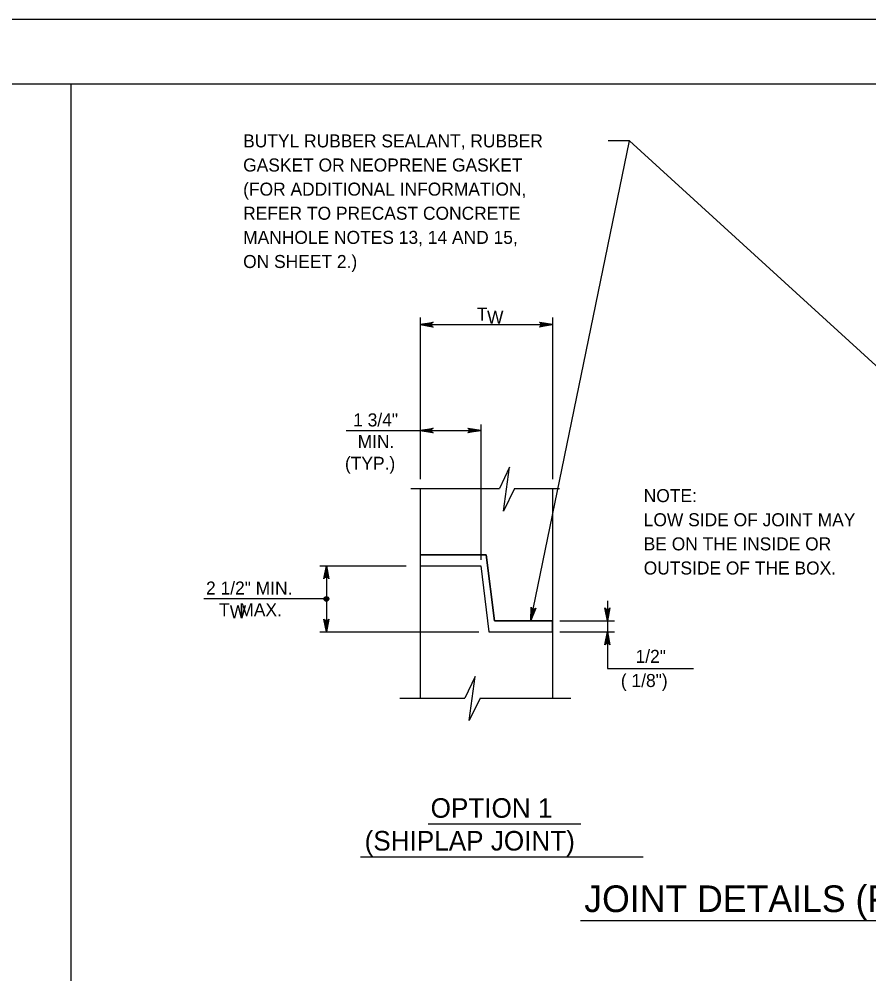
# Model space of a CAD drawing. Extents: x 2106427 to 2114911, y 988717 to 990787.
# Drawn here: x 2112951 to 2113594, y 990066 to 990787 of the extents above; entities that cross this region are included whole.
import ezdxf

# ---------------------------------------------------------------- set-up
doc = ezdxf.new("R2010")
doc.units = 0
for name, color, linetype in [('1', 7, 'Continuous'), ('3', 7, 'Continuous'), ('PLT-BNDY', 7, 'Continuous')]:
    doc.layers.add(name, color=color, linetype=linetype)

msp = doc.modelspace()

# ---------------------------------------------------------------- linework, layer by layer
at = {"layer": '1'}
for p, q in [((2112990.34, 990738.11), (2112990.34, 989231.02)), ((2113668.04, 990462.73), (2113413.04, 990695.31)), ((2113254.61, 990561.73), (2113254.61, 990439.56)), ((2113254.61, 990556.37), (2113354.61, 990556.37)), ((2113354.61, 990561.73), (2113354.61, 990439.56)), ((2113300.45, 990480.77), (2113300.45, 990378.46)), ((2113198.59, 990476.36), (2113300.45, 990476.36)), ((2113247.58, 990432.37), (2113314.54, 990432.37)), ((2113254.61, 990432.37), (2113254.61, 990274.03)), ((2113326.08, 990432.37), (2113360.05, 990432.37)), ((2113354.61, 990432.37), (2113354.61, 990274.03)), ((2113254.61, 990382.37), (2113304.61, 990382.37)), ((2113304.61, 990382.37), (2113310.85, 990332.37)), ((2113178.77, 990374.03), (2113244.11, 990374.03)), ((2113183.67, 990374.03), (2113183.67, 990324.03)), ((2113254.61, 990374.03), (2113300.45, 990374.03)), ((2113300.45, 990374.03), (2113306.69, 990324.03)), ((2113183.67, 990349.03), (2113090.84, 990349.03)), ((2113396.29, 990347.49), (2113396.29, 990296.46)), ((2113310.85, 990332.37), (2113354.61, 990332.37)), ((2113360.28, 990332.37), (2113401.55, 990332.37)), ((2113178.77, 990324.03), (2113298.92, 990324.03)), ((2113306.69, 990324.03), (2113354.61, 990324.03)), ((2113360.28, 990324.03), (2113401.55, 990324.03)), ((2113396.29, 990296.46), (2113461.34, 990296.46)), ((2113239.18, 990274.03), (2113288.53, 990274.03)), ((2113300.08, 990274.03), (2113368.48, 990274.03)), ((2113260.76, 990179.08), (2113376.11, 990179.08)), ((2113209.46, 990154), (2113423.33, 990154)), ((2113375.97, 990105.8), (2113831.83, 990105.8))]:
    msp.add_line(p, q, dxfattribs=at)
for points in [[(2114651.58, 988887.71), (2114651.58, 990738.11), (2112072.84, 990738.11), (2112072.84, 988887.71), (2114651.58, 988887.71), (2114651.58, 988974.19), (2113995.41, 988974.19), (2113995.41, 989186.39), (2114651.58, 989186.39), (2114651.58, 989281.41), (2113995.41, 989281.41), (2113995.41, 988887.71), (2114253.94, 988887.71), (2114253.94, 988974.19), (2114253.94, 988887.71), (2114506.57, 988887.71), (2114506.57, 988974.19), (2114506.57, 988933.79), (2114651.58, 988933.79)], [(2113338.41, 990332.81), (2113413.04, 990695.31), (2113396.73, 990695.31)], [(2113254.61, 990556.37), (2113264.39, 990558.2), (2113264.01, 990557.94), (2113263.64, 990557.68), (2113263.44, 990557.35), (2113263.25, 990557.02), (2113263.19, 990556.69), (2113263.14, 990556.37), (2113263.19, 990556.04), (2113263.25, 990555.71), (2113263.44, 990555.38), (2113263.64, 990555.05), (2113264.01, 990554.79), (2113264.39, 990554.53), (2113254.61, 990556.37), (2113264.01, 990554.79), (2113263.64, 990555.05), (2113254.61, 990556.37), (2113263.44, 990555.38), (2113263.25, 990555.71), (2113254.61, 990556.37), (2113263.19, 990556.04), (2113263.14, 990556.37), (2113254.61, 990556.37), (2113263.19, 990556.69), (2113263.25, 990557.02), (2113254.61, 990556.37), (2113263.44, 990557.35), (2113263.64, 990557.68), (2113254.61, 990556.37), (2113264.01, 990557.94)], [(2113354.61, 990556.37), (2113344.82, 990554.53), (2113345.2, 990554.79), (2113345.57, 990555.05), (2113345.77, 990555.38), (2113345.96, 990555.71), (2113346.02, 990556.04), (2113346.08, 990556.37), (2113346.02, 990556.69), (2113345.96, 990557.02), (2113345.77, 990557.35), (2113345.57, 990557.68), (2113345.2, 990557.94), (2113344.82, 990558.2), (2113354.61, 990556.37), (2113345.2, 990557.94), (2113345.57, 990557.68), (2113354.61, 990556.37), (2113345.77, 990557.35), (2113345.96, 990557.02), (2113354.61, 990556.37), (2113346.02, 990556.69), (2113346.08, 990556.37), (2113354.61, 990556.37), (2113346.02, 990556.04), (2113345.96, 990555.71), (2113354.61, 990556.37), (2113345.77, 990555.38), (2113345.57, 990555.05), (2113354.61, 990556.37), (2113345.2, 990554.79)], [(2113254.61, 990476.36), (2113264.39, 990478.19), (2113264.01, 990477.93), (2113263.64, 990477.67), (2113263.44, 990477.34), (2113263.25, 990477.01), (2113263.19, 990476.68), (2113263.14, 990476.36), (2113263.19, 990476.03), (2113263.25, 990475.7), (2113263.44, 990475.37), (2113263.64, 990475.04), (2113264.01, 990474.78), (2113264.39, 990474.52), (2113254.61, 990476.36), (2113264.01, 990474.78), (2113263.64, 990475.04), (2113254.61, 990476.36), (2113263.44, 990475.37), (2113263.25, 990475.7), (2113254.61, 990476.36), (2113263.19, 990476.03), (2113263.14, 990476.36), (2113254.61, 990476.36), (2113263.19, 990476.68), (2113263.25, 990477.01), (2113254.61, 990476.36), (2113263.44, 990477.34), (2113263.64, 990477.67), (2113254.61, 990476.36), (2113264.01, 990477.93)], [(2113300.45, 990476.36), (2113290.66, 990474.52), (2113291.04, 990474.78), (2113291.41, 990475.04), (2113291.61, 990475.37), (2113291.8, 990475.7), (2113291.86, 990476.03), (2113291.92, 990476.36), (2113291.86, 990476.68), (2113291.8, 990477.01), (2113291.61, 990477.34), (2113291.41, 990477.67), (2113291.04, 990477.93), (2113290.66, 990478.19), (2113300.45, 990476.36), (2113291.04, 990477.93), (2113291.41, 990477.67), (2113300.45, 990476.36), (2113291.61, 990477.34), (2113291.8, 990477.01), (2113300.45, 990476.36), (2113291.86, 990476.68), (2113291.92, 990476.36), (2113300.45, 990476.36), (2113291.86, 990476.03), (2113291.8, 990475.7), (2113300.45, 990476.36), (2113291.61, 990475.37), (2113291.41, 990475.04), (2113300.45, 990476.36), (2113291.04, 990474.78)], [(2113326.08, 990432.37), (2113317.76, 990415.35), (2113322.29, 990448.65), (2113314.54, 990432.37)], [(2113183.67, 990374.03), (2113185.5, 990364.24), (2113185.24, 990364.62), (2113184.98, 990364.99), (2113184.65, 990365.19), (2113184.32, 990365.38), (2113184, 990365.44), (2113183.67, 990365.5), (2113183.34, 990365.44), (2113183.01, 990365.38), (2113182.68, 990365.19), (2113182.36, 990364.99), (2113182.09, 990364.62), (2113181.83, 990364.24), (2113183.67, 990374.03), (2113182.09, 990364.62), (2113182.36, 990364.99), (2113183.67, 990374.03), (2113182.68, 990365.19), (2113183.01, 990365.38), (2113183.67, 990374.03), (2113183.34, 990365.44), (2113183.67, 990365.5), (2113183.67, 990374.03), (2113184, 990365.44), (2113184.32, 990365.38), (2113183.67, 990374.03), (2113184.65, 990365.19), (2113184.98, 990364.99), (2113183.67, 990374.03), (2113185.24, 990364.62)], [(2113338.41, 990332.81), (2113338.59, 990342.76), (2113338.95, 990341.92), (2113339.51, 990341.4), (2113340.13, 990341.16), (2113340.8, 990341.14), (2113341.52, 990341.39), (2113342.18, 990342.02), (2113338.41, 990332.81), (2113341.52, 990341.39), (2113340.8, 990341.14), (2113338.41, 990332.81), (2113340.13, 990341.16), (2113339.51, 990341.4), (2113338.41, 990332.81), (2113338.95, 990341.92)], [(2113396.29, 990332.37), (2113394.45, 990342.15), (2113394.71, 990341.77), (2113394.98, 990341.4), (2113395.3, 990341.2), (2113395.63, 990341.01), (2113395.96, 990340.95), (2113396.29, 990340.9), (2113396.62, 990340.95), (2113396.94, 990341.01), (2113397.27, 990341.2), (2113397.6, 990341.4), (2113397.86, 990341.77), (2113398.12, 990342.15), (2113396.29, 990332.37), (2113397.86, 990341.77), (2113397.6, 990341.4), (2113396.29, 990332.37), (2113397.27, 990341.2), (2113396.94, 990341.01), (2113396.29, 990332.37), (2113396.62, 990340.95), (2113396.29, 990340.9), (2113396.29, 990332.37), (2113395.96, 990340.95), (2113395.63, 990341.01), (2113396.29, 990332.37), (2113395.3, 990341.2), (2113394.98, 990341.4), (2113396.29, 990332.37), (2113394.71, 990341.77)], [(2113183.67, 990324.03), (2113181.83, 990333.81), (2113182.09, 990333.43), (2113182.36, 990333.06), (2113182.68, 990332.86), (2113183.01, 990332.67), (2113183.34, 990332.61), (2113183.67, 990332.56), (2113184, 990332.61), (2113184.32, 990332.67), (2113184.65, 990332.86), (2113184.98, 990333.06), (2113185.24, 990333.43), (2113185.5, 990333.81), (2113183.67, 990324.03), (2113185.24, 990333.43), (2113184.98, 990333.06), (2113183.67, 990324.03), (2113184.65, 990332.86), (2113184.32, 990332.67), (2113183.67, 990324.03), (2113184, 990332.61), (2113183.67, 990332.56), (2113183.67, 990324.03), (2113183.34, 990332.61), (2113183.01, 990332.67), (2113183.67, 990324.03), (2113182.68, 990332.86), (2113182.36, 990333.06), (2113183.67, 990324.03), (2113182.09, 990333.43)], [(2113396.29, 990324.03), (2113398.12, 990314.24), (2113397.86, 990314.62), (2113397.6, 990314.99), (2113397.27, 990315.19), (2113396.94, 990315.38), (2113396.62, 990315.44), (2113396.29, 990315.5), (2113395.96, 990315.44), (2113395.63, 990315.38), (2113395.3, 990315.19), (2113394.98, 990314.99), (2113394.71, 990314.62), (2113394.45, 990314.24), (2113396.29, 990324.03), (2113394.71, 990314.62), (2113394.98, 990314.99), (2113396.29, 990324.03), (2113395.3, 990315.19), (2113395.63, 990315.38), (2113396.29, 990324.03), (2113395.96, 990315.44), (2113396.29, 990315.5), (2113396.29, 990324.03), (2113396.62, 990315.44), (2113396.94, 990315.38), (2113396.29, 990324.03), (2113397.27, 990315.19), (2113397.6, 990314.99), (2113396.29, 990324.03), (2113397.86, 990314.62)], [(2113300.08, 990274.03), (2113291.75, 990257.01), (2113296.28, 990290.31), (2113288.53, 990274.03)]]:
    msp.add_lwpolyline(points, dxfattribs=at)
msp.add_lwpolyline([(2113254.61, 990382.37), (2113254.61, 990374.03), (2113300.45, 990374.03), (2113306.69, 990324.03), (2113354.61, 990324.03), (2113354.61, 990332.37), (2113310.85, 990332.37), (2113304.61, 990382.37)], close=True, dxfattribs=at)
for radius in [1.75, 1.31, 0.875, 0.437]:
    msp.add_circle((2113183.67, 990349.03), radius, dxfattribs=at)
at = {"layer": 'PLT-BNDY'}
msp.add_lwpolyline([(2111944.88, 990787.32), (2114704.07, 990787.32), (2114704.07, 988838.5), (2111944.88, 988838.5)], close=True, dxfattribs=at)

# ---------------------------------------------------------------- texts
at = {"layer": '3'}
for s, height, p in [('BUTYL RUBBER SEALANT, RUBBER', 9.8425, (2113120.7, 990690.34)), ('GASKET OR NEOPRENE GASKET ', 9.8425, (2113120.7, 990672.1)), ('(FOR ADDITIONAL INFORMATION,', 9.8425, (2113120.7, 990653.86)), ('REFER TO PRECAST CONCRETE ', 9.8425, (2113120.7, 990635.63)), ('MANHOLE NOTES 13, 14 AND 15,', 9.8425, (2113120.7, 990617.39)), ('ON SHEET 2.)', 9.8425, (2113120.7, 990599.15)), ('T ', 9.843, (2113297.46, 990559.33)), ('W', 9.84, (2113305.23, 990557.11)), ('1 3/4"', 9.843, (2113203.93, 990479.41)), ('MIN.', 9.843, (2113207.34, 990463.01)), ('(TYP.)', 9.843, (2113197.73, 990446.6)), ('NOTE:', 9.843, (2113423.73, 990422.18)), ('LOW SIDE OF JOINT MAY', 9.8425, (2113423.73, 990403.94)), ('BE ON THE INSIDE OR', 9.8425, (2113423.73, 990385.7)), ('OUTSIDE OF THE BOX.', 9.8425, (2113423.73, 990367.46)), ('2 1/2" MIN.', 9.8425, (2113092.62, 990352.31)), ('T  MAX.', 9.843, (2113102.46, 990335.91)), ('W', 9.84, (2113110.58, 990334.41)), ('1/2"', 9.843, (2113417.57, 990300.66)), ('( 1/8")', 9.843, (2113406.45, 990282.42)), ('OPTION 1', 14.764, (2113262.54, 990183.58)), ('(SHIPLAP JOINT)', 14.7638, (2113212.61, 990158.82)), ('JOINT DETAILS (PRECAST)', 20.1575, (2113378.77, 990112.29))]:
    msp.add_text(s, height=height, dxfattribs=at).set_placement(p)

doc.saveas('drawing.dxf')
